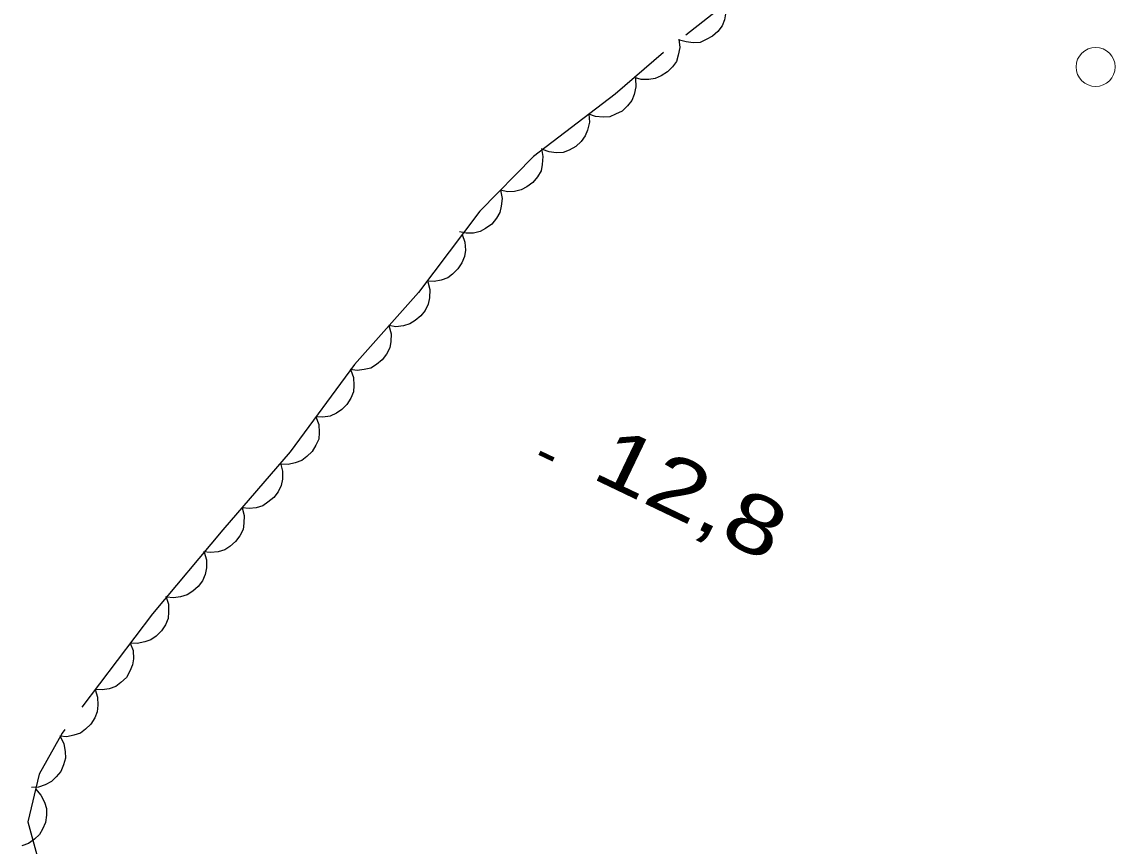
# Model space of a CAD drawing. Extents: x 355726 to 357533, y 5103782 to 5105258.
# Drawn here: x 356149.37 to 356177.4, y 5104844.99 to 5104866.12 of the extents above; entities that cross this region are included whole.
import ezdxf

# ---------------------------------------------------------------- set-up
doc = ezdxf.new("R2010")
doc.units = 0
doc.header["$LTSCALE"] = 0.6
doc.linetypes.add('DOT_DASHED', pattern=[7.7, 5, -1.2, 0.3, -1.2])
for name, color, linetype, lineweight in [('3', 7, 'Continuous', 140), ('36', 7, 'Continuous', 13), ('44', 7, 'Continuous', 25)]:
    doc.layers.add(name, color=color, linetype=linetype, lineweight=lineweight)

msp = doc.modelspace()

# ---------------------------------------------------------------- linework, layer by layer
at = {"layer": '3'}
msp.add_line((356162.64, 5104855.07), (356163, 5104854.9), dxfattribs=at)
at = {"layer": '36'}
msp.add_circle((356176.899, 5104864.96), 0.5, dxfattribs=at)
at = {"layer": '44', "linetype": 'DOT_DASHED'}
msp.add_lwpolyline([(356168.75, 5104867.63), (356165.82, 5104865.33), (356164.58, 5104864.26), (356162.49, 5104862.66), (356161.11, 5104861.26), (356159.54, 5104859.18), (356157.9, 5104857.33), (356156.25, 5104855.09), (356154.52, 5104853.09), (356152.72, 5104850.94), (356150.4, 5104847.88), (356149.81, 5104846.83), (356149.52, 5104845.61), (356149.78, 5104844.67), (356152.64, 5104839.9)], dxfattribs=at)
at = {"layer": '44'}
for points in [[(356167.41, 5104866.58), (356167.42, 5104866.37), (356167.38, 5104866.17), (356167.32, 5104866.01), (356167.21, 5104865.87), (356167.08, 5104865.75), (356166.91, 5104865.66), (356166.76, 5104865.59), (356166.58, 5104865.58), (356166.4, 5104865.6), (356166.23, 5104865.65)], [(356166.21, 5104865.67), (356166.24, 5104865.46), (356166.2, 5104865.26), (356166.15, 5104865.1), (356166.05, 5104864.96), (356165.92, 5104864.83), (356165.76, 5104864.73), (356165.61, 5104864.66), (356165.44, 5104864.64), (356165.25, 5104864.64), (356165.08, 5104864.69)], [(356165.1, 5104864.66), (356165.11, 5104864.45), (356165.07, 5104864.25), (356165.01, 5104864.1), (356164.9, 5104863.96), (356164.76, 5104863.83), (356164.59, 5104863.75), (356164.44, 5104863.68), (356164.27, 5104863.67), (356164.08, 5104863.69), (356163.91, 5104863.75)], [(356163.91, 5104863.75), (356163.92, 5104863.54), (356163.87, 5104863.34), (356163.81, 5104863.19), (356163.71, 5104863.05), (356163.57, 5104862.92), (356163.4, 5104862.83), (356163.25, 5104862.77), (356163.07, 5104862.76), (356162.89, 5104862.78), (356162.72, 5104862.84)], [(356162.69, 5104862.87), (356162.73, 5104862.66), (356162.71, 5104862.46), (356162.68, 5104862.3), (356162.59, 5104862.14), (356162.47, 5104862), (356162.32, 5104861.89), (356162.17, 5104861.81), (356162, 5104861.77), (356161.82, 5104861.76), (356161.64, 5104861.8)], [(356161.64, 5104861.8), (356161.68, 5104861.59), (356161.66, 5104861.39), (356161.62, 5104861.23), (356161.54, 5104861.08), (356161.42, 5104860.93), (356161.26, 5104860.82), (356161.12, 5104860.74), (356160.95, 5104860.7), (356160.76, 5104860.7), (356160.59, 5104860.73)], [(356160.66, 5104860.66), (356160.73, 5104860.47), (356160.74, 5104860.26), (356160.72, 5104860.1), (356160.65, 5104859.94), (356160.55, 5104859.78), (356160.41, 5104859.65), (356160.29, 5104859.55), (356160.12, 5104859.49), (356159.94, 5104859.46), (356159.76, 5104859.47)], [(356159.78, 5104859.45), (356159.83, 5104859.25), (356159.82, 5104859.04), (356159.79, 5104858.88), (356159.71, 5104858.72), (356159.6, 5104858.58), (356159.45, 5104858.46), (356159.32, 5104858.37), (356159.15, 5104858.32), (356158.96, 5104858.3), (356158.78, 5104858.33)], [(356158.78, 5104858.33), (356158.84, 5104858.12), (356158.83, 5104857.92), (356158.8, 5104857.76), (356158.72, 5104857.6), (356158.61, 5104857.45), (356158.46, 5104857.33), (356158.32, 5104857.24), (356158.15, 5104857.2), (356157.97, 5104857.18), (356157.79, 5104857.2)], [(356157.8, 5104857.19), (356157.87, 5104857), (356157.88, 5104856.79), (356157.87, 5104856.63), (356157.8, 5104856.47), (356157.7, 5104856.31), (356157.57, 5104856.18), (356157.44, 5104856.08), (356157.27, 5104856.01), (356157.09, 5104855.98), (356156.91, 5104855.99)], [(356156.91, 5104855.99), (356156.98, 5104855.79), (356156.99, 5104855.59), (356156.98, 5104855.42), (356156.91, 5104855.26), (356156.81, 5104855.1), (356156.68, 5104854.97), (356156.55, 5104854.87), (356156.38, 5104854.81), (356156.2, 5104854.77), (356156.02, 5104854.78)], [(356156, 5104854.8), (356156.05, 5104854.6), (356156.05, 5104854.39), (356156.02, 5104854.23), (356155.94, 5104854.07), (356155.83, 5104853.92), (356155.68, 5104853.8), (356155.55, 5104853.71), (356155.38, 5104853.66), (356155.2, 5104853.64), (356155.02, 5104853.66)], [(356155.02, 5104853.66), (356155.07, 5104853.46), (356155.06, 5104853.26), (356155.04, 5104853.1), (356154.96, 5104852.94), (356154.85, 5104852.79), (356154.7, 5104852.67), (356154.57, 5104852.58), (356154.4, 5104852.53), (356154.21, 5104852.51), (356154.03, 5104852.53)], [(356154.04, 5104852.52), (356154.1, 5104852.32), (356154.1, 5104852.12), (356154.07, 5104851.95), (356154, 5104851.79), (356153.89, 5104851.64), (356153.75, 5104851.52), (356153.61, 5104851.43), (356153.44, 5104851.38), (356153.26, 5104851.35), (356153.08, 5104851.37)], [(356153.06, 5104851.39), (356153.13, 5104851.19), (356153.13, 5104850.99), (356153.12, 5104850.82), (356153.05, 5104850.66), (356152.95, 5104850.5), (356152.81, 5104850.37), (356152.68, 5104850.27), (356152.52, 5104850.22), (356152.33, 5104850.18), (356152.15, 5104850.19)], [(356152.15, 5104850.19), (356152.22, 5104850), (356152.23, 5104849.79), (356152.21, 5104849.63), (356152.14, 5104849.47), (356152.05, 5104849.31), (356151.91, 5104849.18), (356151.78, 5104849.08), (356151.61, 5104849.02), (356151.43, 5104848.99), (356151.25, 5104849)], [(356151.25, 5104849), (356151.31, 5104848.8), (356151.32, 5104848.6), (356151.3, 5104848.43), (356151.24, 5104848.27), (356151.14, 5104848.11), (356151, 5104847.98), (356150.87, 5104847.88), (356150.7, 5104847.83), (356150.52, 5104847.79), (356150.34, 5104847.8)], [(356150.35, 5104847.8), (356150.45, 5104847.61), (356150.48, 5104847.41), (356150.49, 5104847.24), (356150.44, 5104847.07), (356150.37, 5104846.9), (356150.25, 5104846.76), (356150.13, 5104846.64), (356149.97, 5104846.56), (356149.8, 5104846.5), (356149.62, 5104846.49)], [(356149.72, 5104846.45), (356149.86, 5104846.29), (356149.95, 5104846.11), (356150, 5104845.95), (356150, 5104845.78), (356149.98, 5104845.59), (356149.9, 5104845.42), (356149.82, 5104845.28), (356149.69, 5104845.16), (356149.54, 5104845.05), (356149.37, 5104844.99)]]:
    msp.add_lwpolyline(points, dxfattribs=at)

# ---------------------------------------------------------------- texts
at = {"layer": '3', "width": 1.3}
msp.add_text('12,8   ', height=1.5, rotation=334.423, dxfattribs=at).set_placement((356163.93, 5104854.44))

doc.saveas('drawing.dxf')
